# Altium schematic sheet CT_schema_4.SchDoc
size 283 x 147 mm
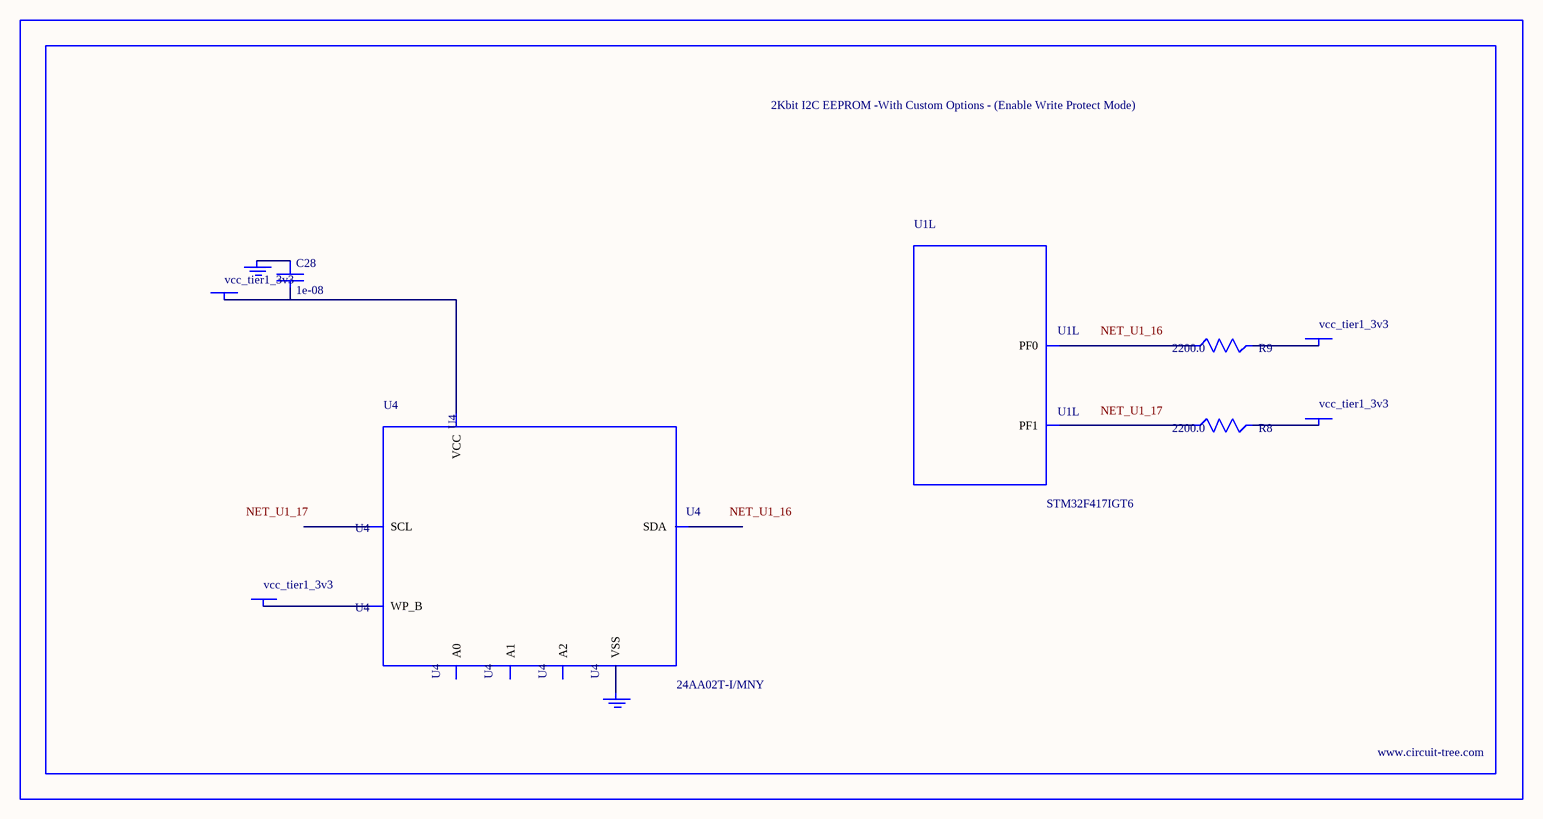
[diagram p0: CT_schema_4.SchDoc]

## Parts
BORDER3  (no value)
C28  1e-08  [C0402]
GND_INSTANCE_3_0  (no value)
GND_INSTANCE_3_1  (no value)
POWER_INSTANCE_3_0  vcc_tier1_3v3
POWER_INSTANCE_3_1  vcc_tier1_3v3
POWER_INSTANCE_3_2  vcc_tier1_3v3
POWER_INSTANCE_3_3  vcc_tier1_3v3
R8  2200.0  [R0603]
R9  2200.0  [R0603]
U1  STM32F417IGT6  [LQFP176]  (part L of 16)
U4  24AA02T-I/MNY  [TDFN-8/6MM]

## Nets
NetC28_1: C28.1 GND_INSTANCE_3_0.0(GND)
NetC28_2: C28.2 POWER_INSTANCE_3_1.0(PWR) U4.8(VCC)
NetGND_INSTANCE_3_1_0: GND_INSTANCE_3_1.0(GND) U4.4(VSS)
NetPOWER_INSTANCE_3_0_0: POWER_INSTANCE_3_0.0(PWR) U4.7(WP_B)
NetPOWER_INSTANCE_3_2_0: POWER_INSTANCE_3_2.0(PWR) R9.2
NetPOWER_INSTANCE_3_3_0: POWER_INSTANCE_3_3.0(PWR) R8.2
NetR8_1: R8.1 U1.17(PF1)
NetR9_1: R9.1 U1.16(PF0)

Not connected (* = marked no-connect by the designer): U4 1(A0) 2(A1) 3(A2) 5(SDA) 6(SCL)

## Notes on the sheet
- Labels drawn without touching a wire or pin: NET_U1_16, NET_U1_17

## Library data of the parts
BORDER3 = BORDER_PAGE3
C28 = C0402C103K3RAC
GND_INSTANCE_3_0 GND_INSTANCE_3_1 = GND
POWER_INSTANCE_3_0-POWER_INSTANCE_3_3 = PWR
R8 R9 = RC0603JR-072K2L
